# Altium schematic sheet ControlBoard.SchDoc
size A3; SheetNumber: 1; SheetTotal: 1
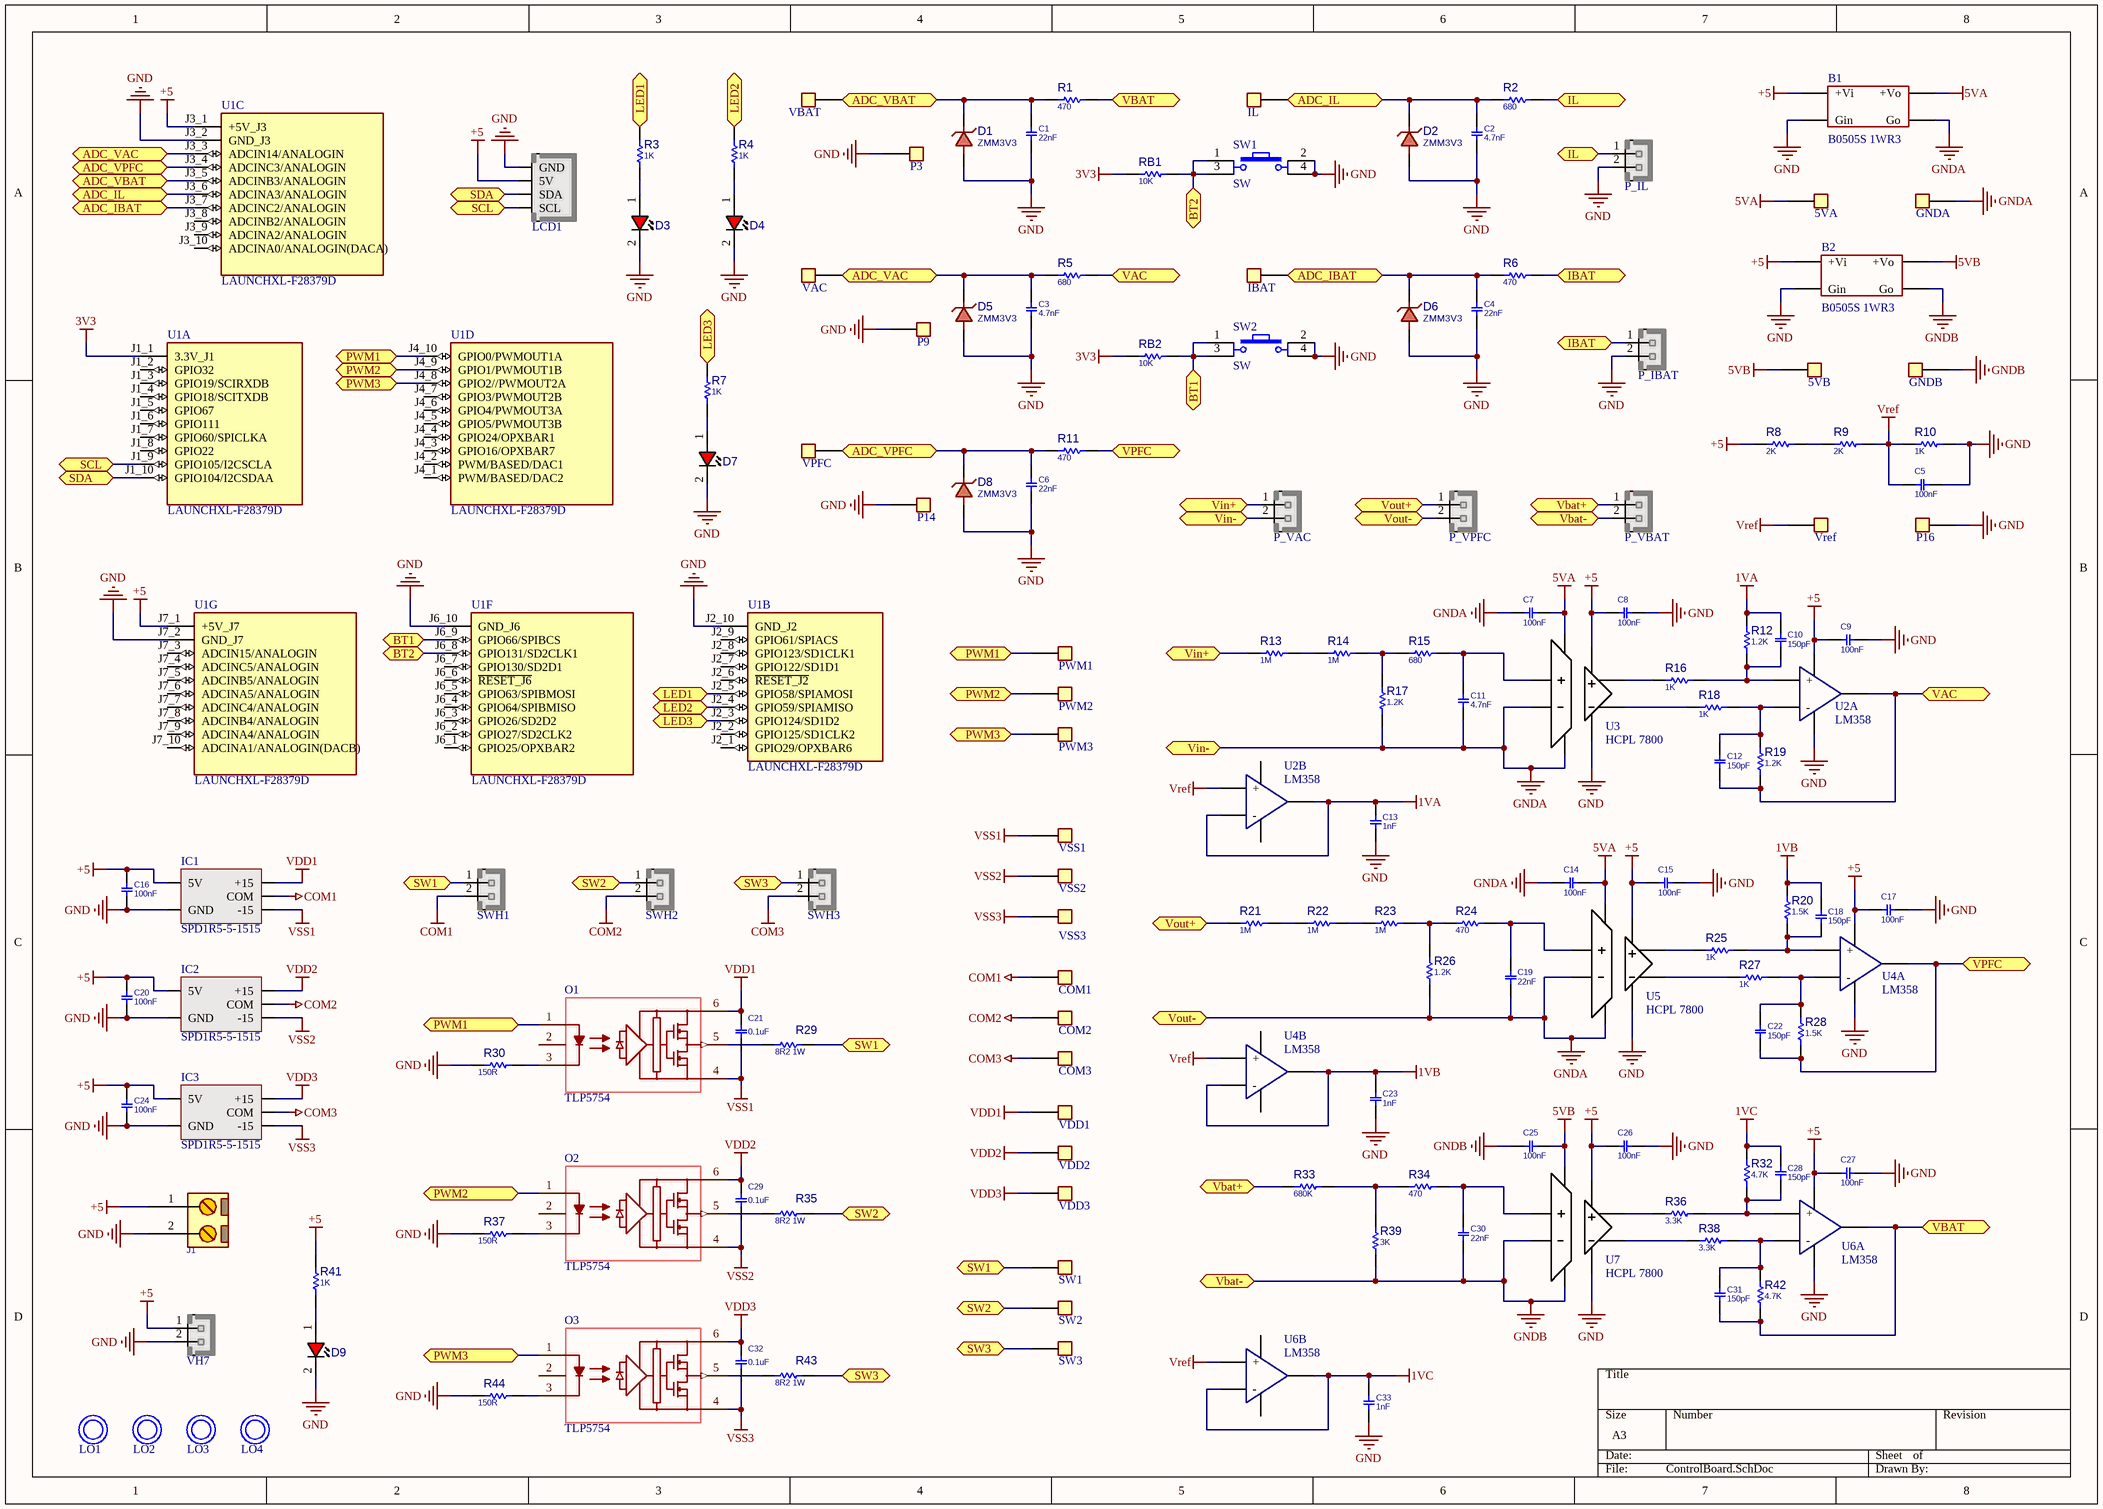
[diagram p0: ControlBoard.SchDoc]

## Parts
(Parts that share a designator on the sheet are numbered #1, #2 ... from top to bottom, then left to right.)
5VA  test PCB  [tp_red_1p]  (value not drawn)
5VB  test PCB  [tp_red_1p]  (value not drawn)
B1  B0505S 1WR3  [B0505S]
B2  B0505S 1WR3  [B0505S]
C1  22nF  [cap_0805]
C2  4.7nF  [cap_0805]
C3  4.7nF  [cap_0805]
C4  22nF  [cap_0805]
C5  100nF  [cap_0805]
C6  22nF  [cap_0805]
C7  100nF  [cap_0805]
C8  100nF  [cap_0805]
C9  100nF  [cap_0805]
C10  150pF  [cap_0805]
C11  4.7nF  [cap_0805]
C12  150pF  [cap_0805]
C13  1nF  [cap_0805]
C14  100nF  [cap_0805]
C15  100nF  [cap_0805]
C16  100nF  [cap_0805]
C17  100nF  [cap_0805]
C18  150pF  [cap_0805]
C19  22nF  [cap_0805]
C20  100nF  [cap_0805]
C21  0.1uF  [cap_0805]
C22  150pF  [cap_0805]
C23  1nF  [cap_0805]
C24  100nF  [cap_0805]
C25  100nF  [cap_0805]
C26  100nF  [cap_0805]
C27  100nF  [cap_0805]
C28  150pF  [cap_0805]
C29  0.1uF  [cap_0805]
C30  22nF  [cap_0805]
C31  150pF  [cap_0805]
C32  0.1uF  [cap_0805]
C33  1nF  [cap_0805]
COM1  test PCB  [tp_white_1p]  (value not drawn)
COM2  test PCB  [tp_white_1p]  (value not drawn)
COM3  test PCB  [tp_white_1p]  (value not drawn)
D1  ZMM3V3  [D_SOD80]
D2  ZMM3V3  [D_SOD80]
D3  (no value)  [LED0805RED]
D4  (no value)  [LED0805RED]
D5  ZMM3V3  [D_SOD80]
D6  ZMM3V3  [D_SOD80]
D7  (no value)  [LED0805RED]
D8  ZMM3V3  [D_SOD80]
D9  (no value)  [LED0805RED]
GNDA  test PCB  [Tp_black_1p]  (value not drawn)
GNDB  test PCB  [Tp_black_1p]  (value not drawn)
IBAT  test PCB  [tp_yellow_1p]  (value not drawn)
IC1  SPD1R5-5-1515  [SPS1R5]
IC2  SPD1R5-5-1515  [SPS1R5]
IC3  SPD1R5-5-1515  [SPS1R5]
IL  test PCB  [tp_yellow_1p]  (value not drawn)
J1  CONN_TB2  [TBG_2]  (value not drawn)
LCD1  HHDR_4  [XH_4]  (value not drawn)
LO1  LO KHOAN  [SCMH_M3P5FT]  (value not drawn)
LO2  LO KHOAN  [SCMH_M3P5FT]  (value not drawn)
LO3  LO KHOAN  [SCMH_M3P5FT]  (value not drawn)
LO4  LO KHOAN  [SCMH_M3P5FT]  (value not drawn)
O1  TLP5754  [TLP5754]
O2  TLP5754  [TLP5754]
O3  TLP5754  [TLP5754]
P3  test PCB  [Tp_black_1p]  (value not drawn)
P9  test PCB  [Tp_black_1p]  (value not drawn)
P14  test PCB  [Tp_black_1p]  (value not drawn)
P16  test PCB  [Tp_black_1p]  (value not drawn)
P_IBAT  HHDR_2  [XH_2]  (value not drawn)
P_IL  HHDR_2  [XH_2]  (value not drawn)
P_VAC  HHDR_2  [VH-2]  (value not drawn)
P_VBAT  HHDR_2  [VH-2]  (value not drawn)
P_VPFC  HHDR_2  [VH-2]  (value not drawn)
PWM1  test PCB  [tp_yellow_1p]  (value not drawn)
PWM2  test PCB  [tp_yellow_1p]  (value not drawn)
PWM3  test PCB  [tp_yellow_1p]  (value not drawn)
R1  470  [R0805]
R2  680  [R0805]
R3  1K  [R0805]
R4  1K  [R0805]
R5  680  [R0805]
R6  470  [R0805]
R7  1K  [R0805]
R8  2K  [R0805]
R9  2K  [R0805]
R10  1K  [R0805]
R11  470  [R0805]
R12  1.2K  [R0805]
R13  1M  [R1206]
R14  1M  [R1206]
R15  680  [R0805]
R16  1K  [R0805]
R17  1.2K  [R1206]
R18  1K  [R0805]
R19  1.2K  [R0805]
R20  1.5K  [R0805]
R21  1M  [R1206]
R22  1M  [R1206]
R23  1M  [R1206]
R24  470  [R0805]
R25  1K  [R0805]
R26  1.2K  [R1206]
R27  1K  [R0805]
R28  1.5K  [R0805]
R29  8R2 1W  [R2512]
R30  150R  [R0805]
R32  4.7K  [R0805]
R33  680K  [R0805]
R34  470  [R0805]
R35  8R2 1W  [R2512]
R36  3.3K  [R0805]
R37  150R  [R0805]
R38  3.3K  [R0805]
R39  3K  [R0805]
R41  1K  [R0805]
R42  4.7K  [R0805]
R43  8R2 1W  [R2512]
R44  150R  [R0805]
RB1  10K  [R0805]
RB2  10K  [R0805]
SW1#1  SW  [SWPBS_SPDT_6X6X5]
SW1#2  test PCB  [Tp_blue_1p]  (value not drawn)
SW2#1  SW  [SWPBS_SPDT_6X6X5]
SW2#2  test PCB  [Tp_blue_1p]  (value not drawn)
SW3  test PCB  [Tp_blue_1p]  (value not drawn)
SWH1  HHDR_2  [VH-2]  (value not drawn)
SWH2  HHDR_2  [VH-2]  (value not drawn)
SWH3  HHDR_2  [VH-2]  (value not drawn)
U1  LAUNCHXL-F28379D  [MOD_LC-F28379D]  (parts A,B,C,D,F,G of 8)
U2  LM358  [SOIC-8]  (parts A,B of 2)
U3  HCPL 7800  [SOP-8P]
U4  LM358  [SOIC-8]  (parts A,B of 2)
U5  HCPL 7800  [SOP-8P]
U6  LM358  [SOIC-8]  (parts A,B of 2)
U7  HCPL 7800  [SOP-8P]
VAC  test PCB  [tp_yellow_1p]  (value not drawn)
VBAT  test PCB  [tp_yellow_1p]  (value not drawn)
VDD1  test PCB  [tp_red_1p]  (value not drawn)
VDD2  test PCB  [tp_red_1p]  (value not drawn)
VDD3  test PCB  [tp_red_1p]  (value not drawn)
VH7  HHDR_2  [VH-2]  (value not drawn)
VPFC  test PCB  [tp_yellow_1p]  (value not drawn)
Vref  test PCB  [tp_red_1p]  (value not drawn)
VSS1  test PCB  [Tp_black_1p]  (value not drawn)
VSS2  test PCB  [Tp_black_1p]  (value not drawn)
VSS3  test PCB  [Tp_black_1p]  (value not drawn)

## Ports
ADC_IBAT (bidir), ADC_IL (bidir), ADC_VAC (bidir), ADC_VBAT (bidir), ADC_VPFC (bidir), BT1 (bidir), BT2 (bidir), IBAT (bidir), IL (bidir), LED1 (bidir), LED2 (bidir), LED3 (bidir), PWM1 (bidir), PWM2 (bidir), PWM3 (bidir), SCL (bidir), SDA (bidir), SW1 (bidir), SW2 (bidir), SW3 (bidir), VAC (bidir), VBAT (bidir), Vbat+ (bidir), Vbat- (bidir), Vin+ (bidir), Vin- (bidir), Vout+ (bidir), Vout- (bidir), VPFC (bidir)

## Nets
1VA: C10.2 C13.2 R12.2 U2.6(-) U2.7(OUT2)
1VB: C18.2 C23.2 R20.2 U4.6(-) U4.7(OUT2)
1VC: C28.2 C33.2 R32.2 U6.6(-) U6.7(OUT2)
3V3: RB1.1 RB2.1 U1.J1_1(3.3V_J1)
5VA: 5VA.1 B1.4(+Vo) C7.2 C14.2 U3.1(VDD1) U5.1(VDD1)
5VB: 5VB.1 B2.4(+Vo) C25.2 U7.1(VDD1)
+5: B1.2(+Vi) B2.2(+Vi) C8.1 C9.1 C15.1 C16.2 C17.1 C20.2 C24.2 C26.1 C27.1 IC1.1(5V) IC2.1(5V) IC3.1(5V) J1.1 LCD1.2(5V) R8.2 R41.1 U1.J3_1(+5V_J3) U1.J7_1(+5V_J7) U2.8(VCC) U3.8(VDD2) U4.8(VCC) U5.8(VDD2) U6.8(VCC) U7.8(VDD2) VH7.1
COM1: COM1.1 IC1.4(COM) SWH1.2
COM2: COM2.1 IC2.4(COM) SWH2.2
COM3: COM3.1 IC3.4(COM) SWH3.2
GND: B1.1(Gin) B2.1(Gin) C1.1 C2.1 C3.1 C4.1 C5.1 C6.1 C8.2 C9.2 C13.1 C15.2 C16.1 C17.2 C20.1 C23.1 C24.1 C26.2 C27.2 C33.1 D1.1 D2.1 D3.2(CATHODE) D4.2(CATHODE) D5.1 D6.1 D7.2(CATHODE) D8.1 D9.2(CATHODE) IC1.2(GND) IC2.2(GND) IC3.2(GND) J1.2 LCD1.1(GND) P3.1 P9.1 P14.1 P16.1 P_IBAT.2 P_IL.2 R10.1 R30.1 R37.1 R44.1 SW1#1.2 SW1#1.4 SW2#1.2 SW2#1.4 U1.J2_10(GND_J2) U1.J3_2(GND_J3) U1.J6_10(GND_J6) U1.J7_2(GND_J7) U2.4(GND) U3.5(GND2) U4.4(GND) U5.5(GND2) U6.4(GND) U7.5(GND2) VH7.2
GNDA: B1.3(Go) C7.1 C11.1 C14.1 C19.1 GNDA.1 P_VAC.2 P_VPFC.2 R17.1 R26.1 U3.3(-) U3.4(GND1) U5.3(-) U5.4(GND1) ; port Vin-, port Vout-
GNDB: B2.3(Go) C25.1 C30.1 GNDB.1 P_VBAT.2 R39.1 U7.3(-) U7.4(GND1) ; port Vbat-
VDD1: C21.2 IC1.5(+15) O1.6(VCC) VDD1.1
VDD2: C29.2 IC2.5(+15) O2.6(VCC) VDD2.1
VDD3: C32.2 IC3.5(+15) O3.6(VCC) VDD3.1
Vref: C5.2 R9.1 R10.2 U2.5(+) U4.5(+) U6.5(+) Vref.1
VSS1: C21.1 IC1.3(-15) O1.4(GND) VSS1.1
VSS2: C29.1 IC2.3(-15) O2.4(GND) VSS2.1
VSS3: C32.1 IC3.3(-15) O3.4(GND) VSS3.1
ADC_IBAT: C4.2 D6.2 IBAT.1 R6.1 U1.J3_7(ADCINC2/ANALOGIN) ; port ADC_IBAT
ADC_IL: C2.2 D2.2 IL.1 R2.1 U1.J3_6(ADCINA3/ANALOGIN) ; port ADC_IL
ADC_VAC: C3.2 D5.2 R5.1 U1.J3_3(ADCIN14/ANALOGIN) VAC.1 ; port ADC_VAC
ADC_VBAT: C1.2 D1.2 R1.1 U1.J3_5(ADCINB3/ANALOGIN) VBAT.1 ; port ADC_VBAT
ADC_VPFC: C6.2 D8.2 R11.1 U1.J3_4(ADCINC3/ANALOGIN) VPFC.1 ; port ADC_VPFC
BT1: RB2.2 SW2#1.1 SW2#1.3 U1.J6_9(GPIO66/SPIBCS) ; port BT1
BT2: RB1.2 SW1#1.1 SW1#1.3 U1.J6_8(GPIO131/SD2CLK1) ; port BT2
IBAT: P_IBAT.1 R6.2 ; port IBAT
IL: P_IL.1 R2.2 ; port IL
LED1: R3.1 U1.J2_5(GPIO58/SPIAMOSI) ; port LED1
LED2: R4.1 U1.J2_4(GPIO59/SPIAMISO) ; port LED2
LED3: R7.1 U1.J2_3(GPIO124/SD1D2) ; port LED3
PWM1: O1.1(NC) PWM1.1 U1.J4_10(GPIO0/PWMOUT1A) ; port PWM1
PWM2: O2.1(NC) PWM2.1 U1.J4_9(GPIO1/PWMOUT1B) ; port PWM2
PWM3: O3.1(NC) PWM3.1 U1.J4_8(GPIO2//PWMOUT2A) ; port PWM3
SCL: LCD1.4(SCL) U1.J1_9(GPIO105/I2CSCLA) ; port SCL
SDA: LCD1.3(SDA) U1.J1_10(GPIO104/I2CSDAA) ; port SDA
SW1: R29.2 SW1#2.1 SWH1.1 ; port SW1
SW2: R35.2 SW2#2.1 SWH2.1 ; port SW2
SW3: R43.2 SW3.1 SWH3.1 ; port SW3
VAC: C12.1 R5.2 R19.1 U2.1(OUT1) ; port VAC
VBAT: C31.1 R1.2 R42.1 U6.1(OUT1) ; port VBAT
Vbat+: P_VBAT.1 R33.1 ; port Vbat+
Vin+: P_VAC.1 R13.1 ; port Vin+
Vout+: P_VPFC.1 R21.1 ; port Vout+
VPFC: C22.1 R11.2 R28.1 U4.1(OUT1) ; port VPFC
NetC10_1: C10.1 R12.1 R16.2 U2.3(+)
NetC11_2: C11.2 R15.1 U3.2(+)
NetC12_2: C12.2 R18.2 R19.2 U2.2(-)
NetC18_1: C18.1 R20.1 R25.2 U4.3(+)
NetC19_2: C19.2 R24.1 U5.2(+)
NetC22_2: C22.2 R27.2 R28.2 U4.2(-)
NetC28_1: C28.1 R32.1 R36.2 U6.3(+)
NetC30_2: C30.2 R34.1 U7.2(+)
NetC31_2: C31.2 R38.2 R42.2 U6.2(-)
NetD3_1: D3.1(ANODE) R3.2
NetD4_1: D4.1(ANODE) R4.2
NetD7_1: D7.1(ANODE) R7.2
NetD9_1: D9.1(ANODE) R41.2
NetO1_3: O1.3(KATHODE) R30.2
NetO1_5: O1.5(VO) R29.1
NetO2_3: O2.3(KATHODE) R37.2
NetO2_5: O2.5(VO) R35.1
NetO3_3: O3.3(KATHODE) R44.2
NetO3_5: O3.5(VO) R43.1
NetR8_1: R8.1 R9.2
NetR13_2: R13.2 R14.1
NetR14_2: R14.2 R15.2 R17.2
NetR16_1: R16.1 U3.7(+)
NetR18_1: R18.1 U3.6(-)
NetR21_2: R21.2 R22.1
NetR22_2: R22.2 R23.1
NetR23_2: R23.2 R24.2 R26.2
NetR25_1: R25.1 U5.7(+)
NetR27_1: R27.1 U5.6(-)
NetR33_2: R33.2 R34.2 R39.2
NetR36_1: R36.1 U7.7(+)
NetR38_1: R38.1 U7.6(-)

Not connected (* = marked no-connect by the designer): O1 2(ANODE); O2 2(ANODE); O3 2(ANODE); U1 J1_2(GPIO32) J1_3(GPIO19/SCIRXDB) J1_4(GPIO18/SCITXDB) J1_5(GPIO67) J1_6(GPIO111) J1_7(GPIO60/SPICLKA) J1_8(GPIO22) J2_1(GPIO29/OPXBAR6) J2_2(GPIO125/SD1CLK2) J2_6(~{RESET_J2}) J2_7(GPIO122/SD1D1) J2_8(GPIO123/SD1CLK1) J2_9(GPIO61/SPIACS) J3_8(ADCINB2/ANALOGIN) J3_9(ADCINA2/ANALOGIN) J3_10(ADCINA0/ANALOGIN(DACA)) J4_1(PWM/BASED/DAC2) J4_2(PWM/BASED/DAC1) J4_3(GPIO16/OPXBAR7) J4_4(GPIO24/OPXBAR1) J4_5(GPIO5/PWMOUT3B) J4_6(GPIO4/PWMOUT3A) J4_7(GPIO3/PWMOUT2B) J6_1(GPIO25/OPXBAR2) J6_2(GPIO27/SD2CLK2) J6_3(GPIO26/SD2D2) J6_4(GPIO64/SPIBMISO) J6_5(GPIO63/SPIBMOSI) J6_6(~{RESET_J6}) J6_7(GPIO130/SD2D1) J7_3(ADCIN15/ANALOGIN) J7_4(ADCINC5/ANALOGIN) J7_5(ADCINB5/ANALOGIN) J7_6(ADCINA5/ANALOGIN) J7_7(ADCINC4/ANALOGIN) J7_8(ADCINB4/ANALOGIN) J7_9(ADCINA4/ANALOGIN) J7_10(ADCINA1/ANALOGIN(DACB))

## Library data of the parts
5VA 5VB COM1-COM3 GNDA GNDB IBAT IL P3 P9 P14 P16 PWM1-PWM3 SW1#2 SW2#2 SW3 VAC VBAT VDD1-VDD3 VPFC Vref VSS1-VSS3 = test PCB: testpin
B1 B2 = B0505S 1WR3: B0505S 1WR3 Isolated Module DC DC Converter
C1-C33 = CAP SMD: PARAM: -, -%; MANF_P#: MANF_PART#; PARAM2: -V
D1 D2 D5 D6 D8 = DIODE Zener: DESC: DESCRIPTION; PARAM: 75V; PARAM2: 0.3A; MANF_P#: 1N4148
D3 D4 D7 D9 = LED_SMD_0805_RED: LED, SMD, 0805, RED; DESC: DESCRIPTION; MANF_P#: MANF_PART#; PARAM2: 2.2V
IC1-IC3 = SPD1R5-5-1515: Power supply Driver SPD1R5-5-1515 / Efficiency 80% / Input 0.381A / Output 50mA
J1 = CONN_TB2: CONN, TERMINAL BLOCK, 5.08mm pitch
LCD1 = LCD I2C: LCD I2C JST-XH pitch: 2.5mm
O1-O3 = TLP5754: MF: Toshiba Semiconductor; MP: TLP250
P_IBAT P_IL = XH_2: XH 2 JST-XH pitch: 2.5mm
P_VAC P_VBAT P_VPFC SWH1-SWH3 VH7 = VH-2
R1-R30 R32-R39 R41-R44 RB1 RB2 = RES SMD: MANF_P#: WSLP0805R0100FEA; MANF: VISHAY; PARAM: 0.5W, -55~155oC; DESC: DESCRIPTION; DIST#: MOUSER; PARAM2: 1%
SW1#1 SW2#1 = SW4: Switch button 4 pin; Value: Button chip 4 pin
U2 U4 U6 = LM358: LM358 Dual Opamp
U3 U5 U7 = HCPL 7800: HCPL 7800 Isolation Amplifer, Opamp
